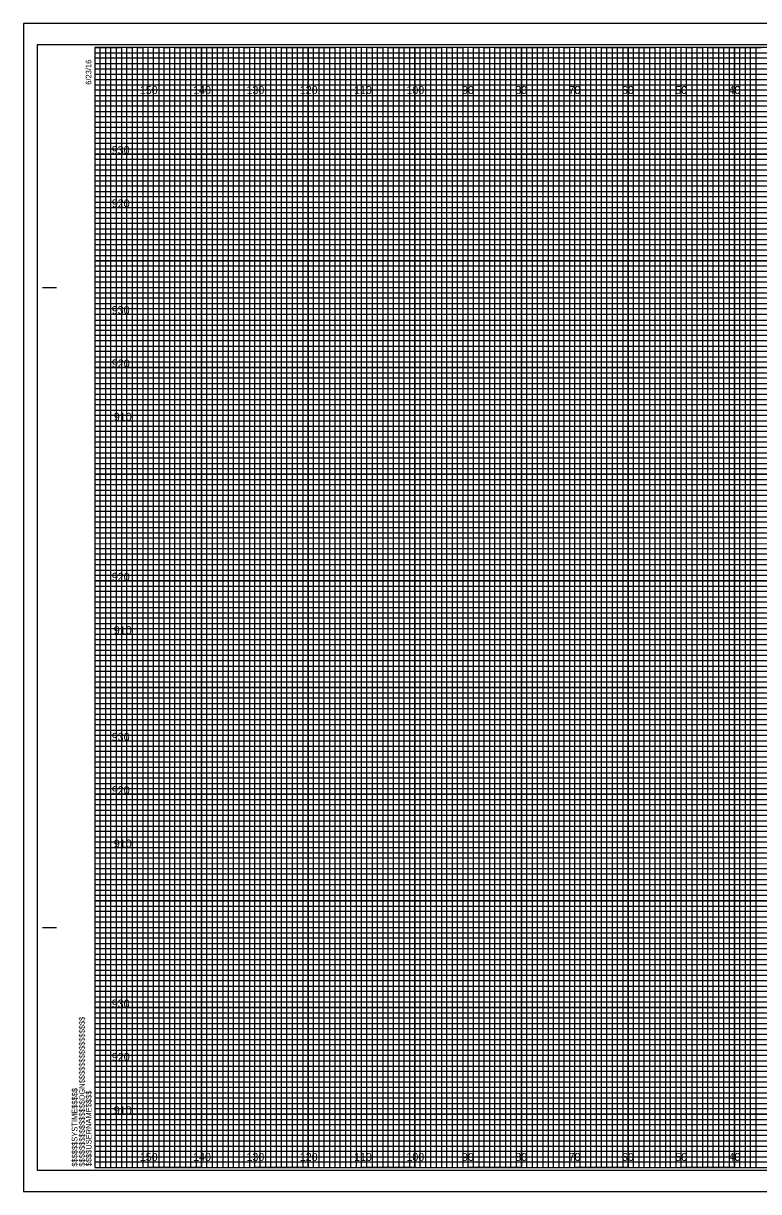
# Model space of a CAD drawing. Extents: x -13 to 323, y 876 to 1094.
# Drawn here: x -13.4 to 124.5, y 875.5 to 1094.5 of the extents above; entities that cross this region are included whole.
import ezdxf

# ---------------------------------------------------------------- set-up
doc = ezdxf.new("R2010")
doc.units = 0
for name, color, linetype in [('Prop XS Elevation Labels', 7, 'Continuous'), ('Prop XS Offset Labels', 7, 'Continuous'), ('Sheet Cross Section CELL', 7, 'Continuous'), ('Sheet Cross Section Grid Major CELL', 7, 'Continuous'), ('Sheet Cross Section Grid Middle CELL', 7, 'Continuous'), ('Sheet Cross Section Grid Minor 1 CELL', 7, 'Continuous'), ('Sheet Cross Section Grid Minor 2 CELL', 7, 'Continuous'), ('Sheet Cutting Line CELL', 7, 'Continuous'), ('Sheet DOT Grid CELL', 7, 'Continuous'), ('Sheet Plot Border Inside CELL', 7, 'Continuous'), ('Sheet Plot Border Outside CELL', 7, 'Continuous')]:
    doc.layers.add(name, color=color, linetype=linetype)

msp = doc.modelspace()

# ---------------------------------------------------------------- linework, layer by layer
at = {"layer": 'Sheet Cross Section CELL'}
for p, q in [((-9.8, 1045), (-7.3, 1045)), ((-9.7, 1045), (-7.2, 1045)), ((-9.8, 925), (-7.3, 925)), ((-9.7, 925), (-7.2, 925)), ((0, 880), (0, 880)), ((0, 880), (0, 880)), ((0, 880), (0, 880)), ((0, 880), (0, 880)), ((0, 880), (0, 880)), ((0, 880), (0, 880)), ((0, 880), (0, 880))]:
    msp.add_line(p, q, dxfattribs=at)
msp.add_lwpolyline([(320, 1090), (0, 1090), (0, 880), (320, 880)], close=True, dxfattribs=at)
at = {"layer": 'Sheet Cross Section Grid Major CELL'}
for p, q in [((10, 1090), (0, 1090)), ((10, 880), (10, 1090)), ((30, 1090), (20, 1090)), ((20, 1090), (20, 880)), ((30, 880), (30, 1090)), ((50, 1090), (40, 1090)), ((40, 1090), (40, 880)), ((50, 880), (50, 1090)), ((70, 1090), (60, 1090)), ((60, 1090), (60, 880)), ((70, 880), (70, 1090)), ((90, 1090), (80, 1090)), ((80, 1090), (80, 880)), ((90, 880), (90, 1090)), ((110, 1090), (100, 1090)), ((100, 1090), (100, 880)), ((110, 880), (110, 1090)), ((130, 1090), (120, 1090)), ((120, 1090), (120, 880)), ((20, 880), (10, 880)), ((40, 880), (30, 880)), ((60, 880), (50, 880)), ((80, 880), (70, 880)), ((100, 880), (90, 880)), ((120, 880), (110, 880))]:
    msp.add_line(p, q, dxfattribs=at)
for points in [[(0, 1080), (320, 1080), (320, 1070), (0, 1070)], [(0, 1060), (320, 1060), (320, 1050), (0, 1050)], [(0, 1040), (320, 1040), (320, 1030), (0, 1030)], [(0, 1020), (320, 1020), (320, 1010), (0, 1010)], [(0, 1000), (320, 1000), (320, 990), (0, 990)], [(0, 980), (320, 980), (320, 970), (0, 970)], [(0, 960), (320, 960), (320, 950), (0, 950)], [(0, 940), (320, 940), (320, 930), (0, 930)], [(0, 920), (320, 920), (320, 910), (0, 910)], [(0, 900), (320, 900), (320, 890), (0, 890)]]:
    msp.add_lwpolyline(points, dxfattribs=at)
at = {"layer": 'Sheet Cross Section Grid Middle CELL'}
for points in [[(0, 1090), (5, 1090), (5, 880), (15, 880), (15, 1090), (25, 1090), (25, 880), (35, 880), (35, 1090), (45, 1090), (45, 880), (55, 880), (55, 1090), (65, 1090), (65, 880), (75, 880), (75, 1090), (85, 1090), (85, 880), (95, 880), (95, 1090), (105, 1090), (105, 880), (115, 880), (115, 1090), (125, 1090)], [(0, 1085), (275, 1085)], [(0, 1065), (320, 1065), (320, 1075), (0, 1075)], [(0, 1045), (320, 1045), (320, 1055), (0, 1055)], [(0, 1025), (320, 1025), (320, 1035), (0, 1035)], [(0, 1005), (320, 1005), (320, 1015), (0, 1015)], [(0, 985), (320, 985), (320, 995), (0, 995)], [(0, 965), (320, 965), (320, 975), (0, 975)], [(0, 945), (320, 945), (320, 955), (0, 955)], [(0, 925), (320, 925), (320, 935), (0, 935)], [(0, 905), (320, 905), (320, 915), (0, 915)], [(0, 885), (320, 885), (320, 895), (0, 895)]]:
    msp.add_lwpolyline(points, dxfattribs=at)
at = {"layer": 'Sheet Cross Section Grid Minor 1 CELL'}
for p, q in [((0, 1089), (260, 1089)), ((260, 1087.98), (0, 1087.98)), ((0, 1087.98), (0, 1087)), ((0, 1087), (260, 1087)), ((260, 1085.89), (0, 1085.89)), ((0, 1085.89), (0, 1084)), ((0, 1084), (320, 1084))]:
    msp.add_line(p, q, dxfattribs=at)
for points in [[(0, 1083), (270, 1083), (320, 1083), (320, 1082), (0, 1082)], [(0, 1081), (320, 1081), (320, 1079), (0, 1079)], [(0, 1078), (320, 1078), (320, 1077), (0, 1076.98)], [(0, 1076), (320, 1076), (320, 1074), (0, 1074)], [(0, 1073), (320, 1073), (320, 1072), (0, 1072)], [(0, 1071), (320, 1071), (320, 1069), (0, 1069)], [(0, 1068), (320, 1068), (320, 1067), (0, 1067)], [(0, 1066), (320, 1066), (320, 1064), (0, 1064)], [(0, 1063), (320, 1063), (320, 1062), (0, 1062)], [(0, 1061), (320, 1061), (320, 1059), (0, 1059)], [(0, 1058), (320, 1058), (320, 1057), (0, 1057)], [(0, 1056), (320, 1056), (320, 1053.95), (320, 1053), (320, 1052), (0, 1052)], [(0, 1054), (320, 1054), (320, 1053), (0, 1053)], [(0, 1051), (320, 1051), (320, 1049), (0, 1049.03)], [(0, 1049.03), (320, 1049), (320, 1048), (0, 1048)], [(0, 1047), (320, 1047), (320, 1046), (0, 1046)], [(0, 1044), (320, 1044), (320, 1043), (0, 1043)], [(0, 1042), (320, 1042), (320, 1041), (0, 1041)], [(-0.07, 1038.89), (320, 1038.89), (320, 1037.88), (-0.07, 1037.88)], [(0, 1037), (320, 1037), (320, 1036), (0, 1036)], [(0, 1034), (320, 1034), (320, 1033), (0, 1033)], [(0, 1032), (320, 1032), (320, 1031), (0, 1031)], [(0, 1029), (320, 1029), (320, 1028), (0, 1028)], [(0, 1027), (320, 1027), (320, 1026), (0, 1026)], [(0, 1024), (320, 1024), (320, 1023), (0, 1023)], [(0, 1022), (320, 1022), (320, 1021), (0, 1021)], [(0, 1019), (320, 1019), (319.99, 1017.98), (0, 1018)], [(0, 1017), (320, 1017), (320, 1016), (0, 1016)], [(0, 1014), (320, 1014), (320, 1013), (0, 1013)], [(0, 1012), (320, 1012), (320, 1011), (0, 1011)], [(0, 1009), (320, 1009), (320, 1008), (0, 1008)], [(0, 1007), (320, 1007), (320, 1006), (0, 1006)], [(0, 1004), (320, 1004), (320, 1003), (0, 1003)], [(0, 1002), (320, 1002), (320, 1001), (0, 1001)], [(0, 999), (320, 999), (320, 998), (0, 998)], [(0, 996.99), (320.07, 996.91), (320, 996), (0, 996)], [(0, 994), (320, 994), (320, 993), (0, 993)], [(0, 992), (320, 992), (320, 991), (0, 991)], [(0, 989), (320, 989), (320, 988), (0, 988)], [(0, 987), (320, 987), (320, 986), (0, 986)], [(0, 984), (320, 984), (320, 983), (0, 983)], [(0, 982), (320, 982), (320, 981), (0, 981)], [(0, 979), (320, 979), (320, 978), (0, 978)], [(0, 977), (320, 977), (320, 976), (0, 976)], [(0, 974), (320, 974), (320, 973), (0, 973)], [(0, 972), (320, 972), (320, 971), (0, 971)], [(0, 969), (320, 969), (320, 968), (0, 968)], [(0, 967), (320, 967), (320, 966), (0, 966)], [(0, 964), (320, 964), (320, 963), (0, 963)], [(0, 962), (320, 962), (320, 961), (0, 961)], [(0, 959), (320, 959), (319.99, 957.98), (0, 958)], [(0, 957), (320, 957), (320, 956), (0, 956)], [(0, 954), (320, 954), (320, 953), (0, 953)], [(0, 952), (320, 952), (320, 951), (0, 951)], [(0, 949), (320, 949), (320, 948), (0, 948)], [(0, 947), (320, 947), (320, 946), (0, 946)], [(0, 944), (320, 944), (320, 943), (0, 943)], [(0, 942), (320, 942), (320, 941), (0, 941)], [(0, 939), (320, 939), (320, 938), (0, 938)], [(0, 936.99), (320.07, 936.91), (320, 936), (0, 936)], [(0, 934), (320, 934), (320, 933), (0, 933)], [(0, 932), (320, 932), (320, 931), (0, 931)], [(0, 929), (320, 929), (320, 928), (0, 928)], [(0, 927), (320, 927), (320, 926), (0, 926)], [(0, 924), (320, 924), (320, 923), (0, 923)], [(0, 922), (320, 922), (320, 921), (0, 921)], [(0, 919), (320, 919), (320, 918), (0, 918)], [(0, 917), (320, 917), (320, 916), (0, 916)], [(0, 914), (320, 914), (320, 913), (0, 913)], [(0, 912), (320, 912), (320, 911), (0, 911)], [(0, 909), (320, 909), (320, 908), (0, 908)], [(0, 907), (320, 907), (320, 906), (0, 906)], [(0, 904), (320, 904), (320, 903), (0, 903)], [(0, 902), (320, 902), (320, 901), (0, 901)], [(0, 899), (320, 899), (320, 898), (0, 898)], [(0, 897), (320, 897), (320, 896), (0, 896)], [(0, 894), (320, 894), (320, 893), (0, 893)], [(0, 892), (320, 892), (320, 891), (0, 891)], [(0, 889), (320, 889), (320, 888), (0, 888)], [(0, 887), (320, 887), (320, 886), (0, 886)], [(0, 884), (320, 884), (320, 883), (0, 883)], [(0, 882), (320, 882), (320, 881), (0, 881)]]:
    msp.add_lwpolyline(points, dxfattribs=at)
at = {"layer": 'Sheet Cross Section Grid Minor 2 CELL'}
for points in [[(0, 880), (1, 880), (1, 1090), (2, 1090), (2, 880)], [(2, 880), (3, 880), (3, 1090), (4, 1090), (4, 880)], [(5, 880), (6, 880), (6, 1090), (7, 1090), (7, 880)], [(7, 880), (8, 880), (8, 1090), (9, 1090), (9, 880)], [(10, 880), (11, 880), (11, 1090), (12, 1090), (12, 880)], [(12, 880), (13, 880), (13, 1090), (14, 1090), (14, 880)], [(15, 880), (16, 880), (16, 1090), (17, 1090), (17, 880)], [(17, 880), (18, 880), (18, 1090), (19, 1090), (19, 880)], [(20, 880), (21, 880), (21, 1090), (22, 1090), (22, 880)], [(22, 880), (23, 880), (23, 1090), (24, 1090), (24, 880)], [(25, 880), (26, 880), (26, 1090), (27, 1090), (27, 880)], [(27, 880), (28, 880), (28, 1090), (29, 1090), (29, 880)], [(30, 880), (31, 880), (31, 1090), (32, 1090), (32, 880)], [(32, 880), (33, 880), (33, 1090), (34, 1090), (34, 880)], [(35, 880), (36, 880), (36, 1090), (37, 1090), (37, 880)], [(37, 880), (38, 880), (38, 1090), (39, 1090), (39, 880)], [(40, 880), (41, 880), (41, 1090), (42, 1090), (42, 880)], [(42, 880), (43, 880), (43, 1090), (44, 1090), (44, 880)], [(45, 880), (46, 880), (46, 1090), (47, 1090), (47, 880)], [(47, 880), (48, 880), (48, 1090), (49, 1090), (49, 880)], [(50, 880), (51, 880), (51, 1090), (52, 1090), (52, 880)], [(52, 880), (53, 880), (53, 1090), (54, 1090), (54, 880)], [(55, 880), (56, 880), (56, 1090), (57, 1090), (57, 880)], [(57, 880), (58, 880), (58, 1090), (59, 1090), (59, 880)], [(60, 880), (61, 880), (61, 1090), (62, 1090), (62, 880)], [(62, 880), (63, 880), (63, 1090), (64, 1090), (64, 880)], [(65, 880), (66, 880), (66, 1090), (67, 1090), (67, 880)], [(67, 880), (68, 880), (68, 1090), (69, 1090), (69, 880)], [(70, 880), (71, 880), (71, 1090), (72, 1090), (72, 880)], [(72, 880), (73, 880), (73, 1090), (74, 1090), (74, 880)], [(75, 880), (76, 880), (76, 1090), (77, 1090), (77, 880)], [(77, 880), (78, 880), (78, 1090), (79, 1090), (79, 880)], [(80, 880), (81, 880), (81, 1090), (82, 1090), (82, 880)], [(82, 880), (83, 880), (83, 1090), (84, 1090), (84, 880)], [(85, 880), (86, 880), (86, 1090), (87, 1090), (87, 880)], [(87, 880), (88, 880), (88, 1090), (89, 1090), (89, 880)], [(90, 880), (91, 880), (91, 1090), (92, 1090), (92, 880)], [(92, 880), (93, 880), (93, 1090), (94, 1090), (94, 880)], [(95, 880), (96, 880), (96, 1090), (97, 1090), (97, 880)], [(97, 880), (98, 880), (98, 1090), (99, 1090), (99, 880)], [(100, 880), (101, 880), (101, 1090), (102, 1090), (102, 880)], [(102, 880), (103, 880), (103, 1090), (104, 1090), (104, 880)], [(105, 880), (106, 880), (106, 1090), (107, 1090), (107, 880)], [(107, 880), (108, 880), (108, 1090), (109, 1090), (109, 880)], [(110, 880), (111, 880), (111, 1090), (112, 1090), (112, 880)], [(112, 880), (113, 880), (113, 1090), (114, 1090), (114, 880)], [(115, 880), (116, 880), (116, 1090), (117, 1090), (117, 880)], [(117, 880), (118, 880), (118, 1090), (119, 1090), (119, 880)], [(120, 880), (121, 880), (121, 1090), (122, 1090), (122, 880)], [(122, 880), (123, 880), (123, 1090), (124, 1090), (124, 880)]]:
    msp.add_lwpolyline(points, dxfattribs=at)
at = {"layer": 'Sheet Cutting Line CELL'}
for p, q in [((323.3, 1094.5), (-13.4, 1094.5)), ((-13.4, 1094.5), (-13.4, 875.5)), ((-13.4, 875.5), (323.3, 875.5))]:
    msp.add_line(p, q, dxfattribs=at)
at = {"layer": 'Sheet DOT Grid CELL'}
for p, q in [((10, 880), (10, 1090)), ((20, 880), (20, 1090)), ((30, 880), (30, 1090)), ((40, 880), (40, 1090)), ((50, 880), (50, 1090)), ((60, 880), (60, 1090)), ((70, 880), (70, 1090)), ((80, 880), (80, 1090)), ((90, 880), (90, 1090)), ((100, 880), (100, 1090)), ((110, 880), (110, 1090)), ((120, 880), (120, 1090)), ((0, 1080), (320, 1080)), ((0, 1070), (320, 1070)), ((0, 1060), (320, 1060)), ((0, 1050), (320, 1050)), ((0, 1040), (320, 1040)), ((0, 1030), (320, 1030)), ((0, 1020), (320, 1020)), ((0, 1010), (320, 1010)), ((0, 1000), (320, 1000)), ((0, 990), (320, 990)), ((0, 980), (320, 980)), ((0, 970), (320, 970)), ((0, 960), (320, 960)), ((0, 950), (320, 950)), ((0, 940), (320, 940)), ((0, 930), (320, 930)), ((0, 920), (320, 920)), ((0, 910), (320, 910)), ((0, 900), (320, 900)), ((0, 890), (320, 890))]:
    msp.add_line(p, q, dxfattribs=at)
at = {"layer": 'Sheet Plot Border Inside CELL'}
msp.add_lwpolyline([(-10.8, 879.5), (322.4, 879.5), (322.4, 1090.5), (-10.8, 1090.5)], close=True, dxfattribs=at)
at = {"layer": 'Sheet Plot Border Outside CELL'}
msp.add_lwpolyline([(-13.4, 875.5), (323.3, 875.5), (323.3, 1094.5), (-13.4, 1094.5)], close=True, dxfattribs=at)

# ---------------------------------------------------------------- texts
at = {"layer": 'Prop XS Elevation Labels'}
for s, p in [('930', (3.18, 1070)), ('920', (3.19, 1060)), ('930', (3.18, 1040)), ('920', (3.19, 1030)), ('910', (3.57, 1020)), ('920', (3.19, 990)), ('910', (3.57, 980)), ('930', (3.18, 960)), ('920', (3.19, 950)), ('910', (3.57, 940)), ('930', (3.18, 910)), ('920', (3.19, 900)), ('910', (3.57, 890))]:
    msp.add_text(s, height=1.5, dxfattribs=at).set_placement(p)
at = {"layer": 'Prop XS Offset Labels'}
for s, p in [('150', (8.44, 1081.25)), ('140', (18.44, 1081.25)), ('130', (28.44, 1081.25)), ('120', (38.44, 1081.25)), ('110', (48.62, 1081.25)), ('100', (58.44, 1081.25)), ('90', (68.86, 1081.25)), ('80', (78.86, 1081.25)), ('70', (88.86, 1081.25)), ('60', (98.86, 1081.25)), ('50', (108.86, 1081.25)), ('40', (118.86, 1081.25)), ('150', (8.44, 881.25)), ('140', (18.44, 881.25)), ('130', (28.44, 881.25)), ('120', (38.44, 881.25)), ('110', (48.62, 881.25)), ('100', (58.44, 881.25)), ('90', (68.86, 881.25)), ('80', (78.86, 881.25)), ('70', (88.86, 881.25)), ('60', (98.86, 881.25)), ('50', (108.86, 881.25)), ('40', (118.86, 881.25))]:
    msp.add_text(s, height=1.5, dxfattribs=at).set_placement(p)
at = {"layer": 'Sheet Cross Section CELL'}
for s, p in [('6/23/16', (-0.65, 1083)), ('$$$$$$$$$$$$$$$$DGN$$$$$$$$$$$$$$$$', (-1.88, 880.18)), ('$$$$$$SYSTIME$$$$$', (-3.26, 880.18)), ('$$$$USERNAME$$$$', (-0.62, 880.23))]:
    msp.add_text(s, height=1.05, rotation=90, dxfattribs=at).set_placement(p)

doc.saveas('drawing.dxf')
